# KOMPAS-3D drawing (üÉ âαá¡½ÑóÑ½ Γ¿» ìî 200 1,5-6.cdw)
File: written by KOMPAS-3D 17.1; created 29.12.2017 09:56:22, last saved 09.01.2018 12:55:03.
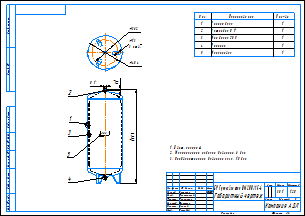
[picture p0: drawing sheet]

Sheet 1: A3, landscape, title-block layout from C:\Лощинин\GRAPHIC.LYT style 1

Title block, sheet 1: name: БР Гранлевел тип НМ 200/1,5-6 / Габаритный чертеж; mass: 38,1; sheets: 1; sheet format: A3; stored path: \\Fsk1\files\АП\20_PKO\02_Насосное направление\Разработка\04_Проекты разные\Баки\КД действующая\Баки Flexcon R\Компас\Чертежи\БР Гранлевел тип НМ 200 1,5-6.cdw; drawn by: Лощинин; checked by: Хантимеров; drawn by, date: 29.12.2017

Views: Проекционный вид 2
Referenced files in \\Fsk1\files\АП\20_PKO\02_Насосное направление\Разработка\04_Проекты разные\Баки\КД действующая\Баки Flexcon R\Компас\: 200 литров.a3d, 16206_Flexcon_200_1-6.m3d
Referenced files in C:\Лощинин\: GRAPHIC.LYT
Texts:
  IvAn
  ADL
  Поз.
  Кол-во
  Корпус бака
  Мембрана SBR
  Патрубок G 1"
  Ниппель
  Маркировка
  АДЛ
  Цвет: красный
  Максимальное рабочее давление: 6 бар
  Предварительное давление газа: 1,5 бар
  ACAD_ISO03W100_RGB_223_127_255_SC_0.063_THICK_0.05
  ACAD_ISO03W100_RGB_223_127_255_SC_1_THICK_0.05
  Лит-Масса-Масштаб
  Материал-Предприятие
  Масштаб
  Изм.
  Лист
  № докум.
  Подп.
  Дата
  Лит.
  Разраб.
  Пров.
  Т.контр.
  Курлыкина
  Листов
  Нач.отд.
  Щетинин
  Н.контр.
  Долгов
  Утв.
  Рашидов
  Компания АДЛ
  Изменение
  Номер документа
  Подпись
  Обозначение документа
  Наименование изделия
  Масса изделия по ГОСТ 2.109-73
  Порядковый номер листа
  Общее количество листов в документе
  Характер работы, выполненной лицом, подписавшим документ
  Наименование или индекс предприятия, выпускающего документ
  Инв. № подл.
  Подп. и дата
  Взам. инв. №
  Инв. № дубл.
  Инвентарный номер подлинника по ГОСТ 2.501-68
  Подпись принявшего подлинник в отдел технической документации
  Инвентарный номер подлинника, взамен которого выпущен данный подлинник
  Инвентарный номер дубликата по ГОСТ 2.502-68
  Подпись принявшего дубликат в отдел технической документации
  Справ. №
  Перв. примен.
  Обозначение документа, взамен или на основании которого выпущен данный документ
  Обозначение документа, в котором впервые записан данный документ
  Подпись лица, копировавшего чертеж
  Обозначение формата листа
Dimensions and other numbers on the sheet: 1; 3; 2; 4; 5; 1296; 21; 1:20; 38,1; 29.12.2017; 16206_Flexcon_200_1-6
